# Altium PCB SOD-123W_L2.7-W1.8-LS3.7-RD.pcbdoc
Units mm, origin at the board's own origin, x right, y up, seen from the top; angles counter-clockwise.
Board outline 16.95 x 14.61 mm, 2 copper layers (Top Layer, Bottom Layer), stack 0 mm thick; 1 components, 0 nets, 2 pads, 0 vias.
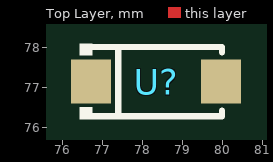
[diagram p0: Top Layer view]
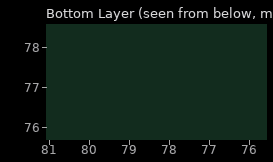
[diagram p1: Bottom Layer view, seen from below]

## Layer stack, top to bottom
Top Layer: signal copper (thickness not stored)
Bottom Layer: signal copper (thickness not stored)

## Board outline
86.804,69.85 69.85,69.85 69.85,84.46 86.804,84.46

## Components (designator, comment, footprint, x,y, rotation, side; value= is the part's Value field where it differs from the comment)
U? "" SOD-123W_L2.7-W1.8-LS3.7-RD 78.327,77.16 r0 top

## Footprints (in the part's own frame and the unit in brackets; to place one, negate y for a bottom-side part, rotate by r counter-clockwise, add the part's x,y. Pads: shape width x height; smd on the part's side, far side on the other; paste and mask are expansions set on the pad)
SOD-123W_L2.7-W1.8-LS3.7-RD [mm]
  rect 1x1.1 smd: 1(-1.627,0) 2(1.627,0)
  silkscreen extent -1.9,-0.94 1.65,0.95

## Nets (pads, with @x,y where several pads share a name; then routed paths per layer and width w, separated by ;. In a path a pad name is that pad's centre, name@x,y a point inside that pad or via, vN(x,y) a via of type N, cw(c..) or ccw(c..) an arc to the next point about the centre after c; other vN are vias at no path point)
pads on no net: U?.1 U?.2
